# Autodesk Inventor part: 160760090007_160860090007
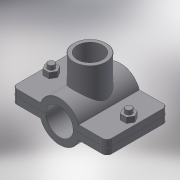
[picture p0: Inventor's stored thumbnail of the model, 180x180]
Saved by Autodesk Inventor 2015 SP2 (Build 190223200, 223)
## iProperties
Created: 2017-05
Part Number: 160760090007_160860090007
Material: Generic
Description: PLASSON SADDLE 90-3/4"
Document SubType Name: Modeling
Designer: KIM
Density: 1 g/cm^3
Appearance: Default
Author: KIM
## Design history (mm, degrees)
derived "16076.ipt"
feature "Solid1::16076.ipt"
feature "Solid2::16076.ipt"
tag "TaggingFeature1"
body "Solid1"
other parameters: "d0" = 99, "d1" = 141, "d2" = 45, "d4" = 105, "d5" = 0, "d6" = 7.05, "d7" = 141, "d8" = 0.1, "d10" = 0, "d11" = 0.9, "d14" = 31.3521, "d20" = 0.9, "d23" = 0.9, "d36" = 13, "d37" = 10.4, "d38" = 53, "d39" = 0, "d40" = 3, "d41" = 5, "d42" = 0, "d43" = 8, "d44" = 3, "d45" = 0, "d46" = 0.9, "d51" = 73, "d52" = 24.117, "d53" = 19, "d54" = 0, "d57" = 0, "d58" = 97.2, "d60" = 0, "d62" = 13, "d63" = 10.4, "d66" = 84.2, "G_" = 24.117, "A_" = 73, "L_" = 141, "L_1" = 105, "l_2" = 19
